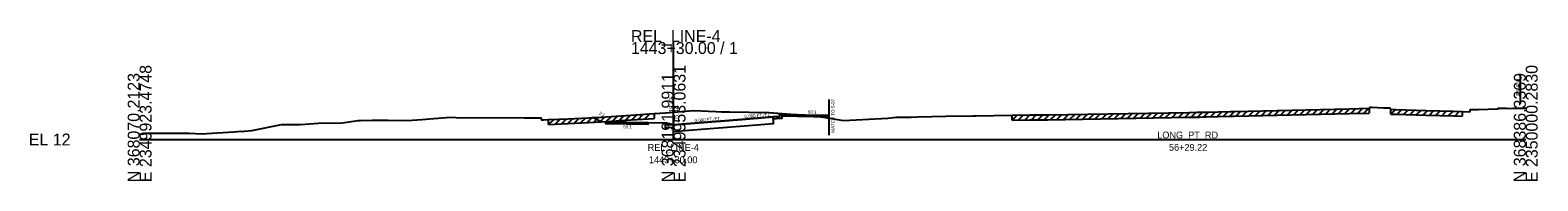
# Model space of a CAD drawing. Extents: x -26 to 2350146, y -10 to 368200.
# Drawn here: x 1974.3 to 2328.2, y 3490.3 to 3525.7 of the extents above; entities that cross this region are included whole.
import ezdxf

# ---------------------------------------------------------------- set-up
doc = ezdxf.new("R2010")
doc.units = 0
for name, color, linetype in [('RD_GPK_XS_Cell', 7, 'Continuous'), ('RD_XS_Base', 7, 'Continuous'), ('RD_XS_CurbBase', 7, 'Continuous'), ('RD_XS_CurbFront', 7, 'Continuous'), ('RD_XS_CurbTop', 7, 'Continuous'), ('RD_XS_EarthShd', 7, 'Continuous'), ('RD_XS_EwShp', 7, 'Continuous'), ('RD_XS_ExGround', 7, 'Continuous'), ('RD_XS_ExPaveRet', 7, 'Continuous'), ('RD_XS_ExRW', 7, 'Continuous'), ('RD_XS_Pave', 7, 'Continuous'), ('RD_XS_PaveShd', 7, 'Continuous'), ('RD_XS_SW', 7, 'Continuous'), ('RD_XS_SWbase', 7, 'Continuous'), ('RD_XS_TieSlope', 7, 'Continuous'), ('RD_XS_TX_Elev_EX', 7, 'Continuous'), ('RD_XS_TX_Elev_PR', 7, 'Continuous'), ('RD_XS_TX_MatchLine', 7, 'Continuous'), ('RD_XS_TX_Slope', 7, 'Continuous'), ('RD_XS_TX_Station', 7, 'Continuous'), ('RD_XS_TX_TOC', 7, 'Continuous')]:
    doc.layers.add(name, color=color, linetype=linetype)

msp = doc.modelspace()

# ---------------------------------------------------------------- linework, layer by layer
at = {"layer": 'RD_GPK_XS_Cell'}
for p, q in [((2125.32, 3500), (2125.32, 3522.86)), ((2000, 3500), (2125.32, 3500)), ((2125.32, 3500), (2325.32, 3500))]:
    msp.add_line(p, q, dxfattribs=at)
at = {"layer": 'RD_XS_Base'}
for p, q in [((2144.86, 3503.36), (2128.86, 3502.08)), ((2148.73, 3503.67), (2144.86, 3503.36)), ((2148.73, 3505.31), (2148.73, 3503.67)), ((2125.32, 3501.8), (2125.32, 3502.92)), ((2128.86, 3502.08), (2125.32, 3501.8))]:
    msp.add_line(p, q, dxfattribs=at)
at = {"layer": 'RD_XS_CurbBase'}
for p, q in [((2123.32, 3503.83), (2123.32, 3502.83)), ((2150.22, 3504.9), (2148.73, 3504.79)), ((2150.72, 3504.9), (2150.22, 3504.9)), ((2150.72, 3505.9), (2150.72, 3504.9)), ((2123.32, 3502.83), (2123.82, 3502.83)), ((2123.82, 3502.83), (2125.32, 3502.92))]:
    msp.add_line(p, q, dxfattribs=at)
at = {"layer": 'RD_XS_CurbFront'}
for p, q in [((2125.32, 3502.92), (2125.32, 3503.42)), ((2148.73, 3504.79), (2148.73, 3505.29))]:
    msp.add_line(p, q, dxfattribs=at)
at = {"layer": 'RD_XS_CurbTop'}
for p, q in [((2123.82, 3503.83), (2123.32, 3503.83)), ((2123.9, 3503.33), (2123.82, 3503.83)), ((2125.32, 3503.42), (2123.9, 3503.33)), ((2125.32, 3503.44), (2125.32, 3503.42)), ((2148.73, 3505.29), (2150.14, 3505.4)), ((2148.73, 3505.31), (2148.73, 3505.29)), ((2150.14, 3505.4), (2150.22, 3505.9)), ((2150.22, 3505.9), (2150.72, 3505.9))]:
    msp.add_line(p, q, dxfattribs=at)
at = {"layer": 'RD_XS_EarthShd'}
for p, q in [((2109.32, 3504.11), (2108.32, 3504.13)), ((2123.32, 3503.83), (2119.32, 3503.91))]:
    msp.add_line(p, q, dxfattribs=at)
at = {"layer": 'RD_XS_EwShp'}
for points in [[(2123.42, 3506.27), (2125.32, 3506.42), (2130.02, 3506.78), (2135.34, 3506.55), (2136.59, 3506.5), (2138.46, 3506.5), (2147.67, 3506.36), (2154.34, 3505.83), (2150.72, 3505.9), (2150.22, 3505.9), (2150.14, 3505.4), (2148.73, 3505.31), (2141.32, 3504.72), (2125.32, 3503.42), (2123.9, 3503.33), (2123.82, 3503.83), (2123.32, 3503.83), (2119.32, 3503.91), (2109.32, 3504.11), (2108.32, 3504.13), (2106.27, 3505.16), (2108.36, 3505.27), (2115.36, 3505.72), (2120.75, 3506.07)], [(2109.32, 3504.11), (2109.32, 3503.78), (2119.32, 3503.58), (2119.32, 3503.91)], [(2125.32, 3503.42), (2123.9, 3503.33), (2123.82, 3503.83), (2123.32, 3503.83), (2123.32, 3502.83), (2123.82, 3502.83), (2125.32, 3502.92)], [(2125.32, 3501.8), (2125.32, 3502.92), (2125.32, 3503.42), (2141.32, 3504.72), (2148.73, 3505.31), (2148.73, 3504.79), (2148.73, 3503.67), (2144.86, 3503.36), (2128.86, 3502.08)], [(2150.72, 3505.57), (2150.72, 3504.9), (2150.22, 3504.9), (2148.73, 3504.79), (2148.73, 3505.31), (2150.14, 3505.4), (2150.22, 3505.9), (2150.72, 3505.9)], [(2154.34, 3505.83), (2158.06, 3505.53), (2159.07, 3505.4), (2150.72, 3505.57), (2150.72, 3505.9)], [(2159.07, 3505.4), (2159.8, 3505.31), (2160.52, 3505.26), (2161.84, 3505.03), (2161.84, 3505.35)]]:
    msp.add_lwpolyline(points, close=True, dxfattribs=at)
at = {"layer": 'RD_XS_ExGround'}
msp.add_lwpolyline([(2000, 3501.25), (2000.38, 3501.29), (2001.98, 3501.46), (2002.55, 3501.5), (2004.55, 3501.5), (2010.26, 3501.49), (2010.63, 3501.5), (2011.6, 3501.46), (2014.52, 3501.35), (2022.11, 3501.77), (2023.81, 3501.96), (2024.19, 3501.92), (2024.58, 3501.96), (2026.37, 3502.15), (2033.32, 3503.5), (2037.76, 3503.49), (2041.95, 3503.83), (2047.54, 3503.9), (2051.32, 3504.5), (2051.81, 3504.5), (2054.55, 3504.51), (2056.8, 3504.51), (2058.36, 3504.51), (2062.81, 3504.5), (2066.25, 3504.69), (2072.91, 3505.28), (2075.62, 3505.11), (2082.34, 3505.17), (2090.29, 3505.08), (2093.59, 3505.1), (2094.15, 3505.09), (2094.32, 3504.59), (2094.9, 3504.62), (2095.99, 3504.66), (2100.61, 3504.88), (2105.35, 3505.11), (2108.36, 3505.27), (2115.36, 3505.72), (2120.75, 3506.07), (2123.42, 3506.27), (2125.32, 3506.42), (2130.02, 3506.78), (2135.34, 3506.55), (2136.59, 3506.5), (2138.46, 3506.5), (2147.67, 3506.36), (2158.06, 3505.53), (2159.8, 3505.31), (2160.52, 3505.26), (2165.16, 3504.44), (2175.59, 3505.02), (2177.67, 3505.28), (2179.39, 3505.27), (2181.05, 3505.28), (2182.62, 3505.3), (2189.24, 3505.5), (2195.52, 3505.52), (2196.26, 3505.53), (2204.8, 3505.7), (2208.92, 3505.79), (2213.11, 3505.79), (2246.21, 3506.36), (2248.09, 3506.4), (2248.78, 3506.41), (2250.35, 3506.45), (2255.98, 3506.58), (2256.88, 3506.6), (2283.86, 3507.21), (2288.59, 3507.32), (2288.78, 3507.62), (2289.2, 3507.62), (2291.95, 3507.47), (2293.02, 3507.42), (2293.44, 3507.42), (2293.64, 3507.12), (2294.83, 3507.08), (2301.92, 3506.82), (2308.39, 3506.67), (2310.37, 3506.6), (2312.16, 3506.52), (2312.35, 3507.02), (2312.94, 3507.02), (2314.12, 3507.04), (2318.82, 3507.2), (2318.82, 3507.35), (2320.84, 3507.37), (2321.14, 3507.31), (2322.36, 3507.35), (2325.32, 3507.38)], dxfattribs=at)
at = {"layer": 'RD_XS_ExPaveRet'}
for p, q in [((2260.3, 3505.54), (2261.47, 3506.71)), ((2261.8, 3505.57), (2262.97, 3506.74)), ((2263.3, 3505.6), (2264.47, 3506.77)), ((2264.8, 3505.64), (2265.97, 3506.81)), ((2266.3, 3505.67), (2267.47, 3506.84)), ((2267.8, 3505.71), (2268.97, 3506.88)), ((2269.3, 3505.74), (2270.47, 3506.91)), ((2270.8, 3505.77), (2271.97, 3506.94)), ((2272.3, 3505.81), (2273.47, 3506.98)), ((2273.8, 3505.84), (2274.97, 3507.01)), ((2275.3, 3505.88), (2276.47, 3507.05)), ((2276.8, 3505.91), (2277.97, 3507.08)), ((2278.3, 3505.94), (2279.47, 3507.11)), ((2279.8, 3505.98), (2280.97, 3507.15)), ((2281.3, 3506.01), (2282.47, 3507.18)), ((2282.8, 3506.05), (2283.97, 3507.22)), ((2284.3, 3506.08), (2285.47, 3507.25)), ((2285.8, 3506.11), (2286.97, 3507.28)), ((2287.3, 3506.15), (2288.47, 3507.32)), ((2288.59, 3507.32), (2288.59, 3506.17)), ((2293.64, 3505.97), (2293.64, 3507.12)), ((2293.64, 3505.97), (2294.74, 3507.08)), ((2295.14, 3505.92), (2296.24, 3507.03)), ((2296.64, 3505.87), (2297.74, 3506.97)), ((2298.14, 3505.81), (2299.24, 3506.92)), ((2299.64, 3505.76), (2300.74, 3506.86)), ((2301.14, 3505.71), (2302.24, 3506.81)), ((2302.64, 3505.66), (2303.75, 3506.78)), ((2304.14, 3505.62), (2305.25, 3506.74)), ((2305.64, 3505.59), (2306.75, 3506.71)), ((2095.99, 3503.52), (2097.19, 3504.72)), ((2095.99, 3503.52), (2095.99, 3504.66)), ((2095.99, 3503.52), (2100.61, 3503.74)), ((2097.49, 3503.59), (2098.69, 3504.79)), ((2098.99, 3503.66), (2100.19, 3504.86)), ((2100.49, 3503.73), (2101.69, 3504.93)), ((2100.61, 3503.74), (2105.35, 3503.97)), ((2101.99, 3503.8), (2103.19, 3505)), ((2103.49, 3503.88), (2104.69, 3505.08)), ((2104.99, 3503.95), (2106.2, 3505.15)), ((2105.35, 3503.97), (2108.36, 3504.13)), ((2106.49, 3504.03), (2107.7, 3505.24)), ((2107.99, 3504.11), (2109.21, 3505.33)), ((2108.36, 3504.13), (2115.36, 3504.58)), ((2109.49, 3504.2), (2110.71, 3505.42)), ((2110.99, 3504.3), (2112.21, 3505.52)), ((2112.49, 3504.4), (2113.71, 3505.62)), ((2113.99, 3504.49), (2115.21, 3505.72)), ((2115.36, 3504.58), (2120.75, 3504.93)), ((2115.49, 3504.59), (2116.71, 3505.81)), ((2116.99, 3504.69), (2118.21, 3505.91)), ((2118.49, 3504.78), (2119.71, 3506)), ((2120.75, 3506.07), (2120.75, 3504.93)), ((2204.8, 3504.56), (2205.97, 3505.72)), ((2204.8, 3504.56), (2204.8, 3505.7)), ((2204.8, 3504.56), (2208.92, 3504.64)), ((2206.3, 3504.59), (2207.47, 3505.76)), ((2207.8, 3504.62), (2208.97, 3505.79)), ((2208.92, 3504.64), (2213.11, 3504.65)), ((2209.3, 3504.64), (2210.45, 3505.79)), ((2210.8, 3504.65), (2211.95, 3505.79)), ((2212.3, 3504.65), (2213.45, 3505.8)), ((2213.11, 3504.65), (2246.21, 3505.22)), ((2213.8, 3504.66), (2214.97, 3505.83)), ((2215.3, 3504.69), (2216.47, 3505.85)), ((2216.8, 3504.72), (2217.97, 3505.88)), ((2218.3, 3504.74), (2219.47, 3505.9)), ((2219.8, 3504.77), (2220.97, 3505.93)), ((2221.3, 3504.79), (2222.47, 3505.96)), ((2222.8, 3504.82), (2223.97, 3505.98)), ((2224.3, 3504.84), (2225.47, 3506.01)), ((2225.8, 3504.87), (2226.97, 3506.03)), ((2227.3, 3504.9), (2228.47, 3506.06)), ((2228.8, 3504.92), (2229.97, 3506.08)), ((2230.3, 3504.95), (2231.47, 3506.11)), ((2231.8, 3504.97), (2232.97, 3506.14)), ((2233.3, 3505), (2234.47, 3506.16)), ((2234.8, 3505.02), (2235.97, 3506.19)), ((2236.3, 3505.05), (2237.47, 3506.21)), ((2237.8, 3505.08), (2238.97, 3506.24)), ((2239.3, 3505.1), (2240.47, 3506.26)), ((2240.8, 3505.13), (2241.97, 3506.29)), ((2242.3, 3505.15), (2243.47, 3506.32)), ((2243.8, 3505.18), (2244.97, 3506.34)), ((2245.3, 3505.2), (2246.47, 3506.37)), ((2246.21, 3505.22), (2248.09, 3505.26)), ((2246.8, 3505.23), (2247.97, 3506.4)), ((2248.09, 3505.26), (2248.78, 3505.27)), ((2248.3, 3505.26), (2249.47, 3506.43)), ((2248.78, 3505.27), (2250.35, 3505.31)), ((2249.8, 3505.29), (2250.97, 3506.46)), ((2250.35, 3505.31), (2255.98, 3505.44)), ((2251.3, 3505.33), (2252.47, 3506.5)), ((2252.8, 3505.36), (2253.97, 3506.53)), ((2254.3, 3505.4), (2255.47, 3506.57)), ((2255.8, 3505.43), (2256.97, 3506.6)), ((2255.98, 3505.44), (2256.88, 3505.46)), ((2256.88, 3505.46), (2283.86, 3506.07)), ((2257.3, 3505.47), (2258.47, 3506.64)), ((2258.8, 3505.5), (2259.97, 3506.67)), ((2283.86, 3506.07), (2288.59, 3506.17)), ((2293.64, 3505.97), (2294.83, 3505.93)), ((2294.83, 3505.93), (2301.92, 3505.68)), ((2301.92, 3505.68), (2308.39, 3505.52)), ((2307.14, 3505.55), (2308.25, 3506.67)), ((2308.39, 3505.52), (2310.37, 3505.46)), ((2308.64, 3505.51), (2309.74, 3506.62)), ((2310.37, 3506.6), (2310.37, 3505.46))]:
    msp.add_line(p, q, dxfattribs=at)
at = {"layer": 'RD_XS_ExRW'}
msp.add_line((2324.08, 3508.37), (2324.08, 3515.37), dxfattribs=at)
at = {"layer": 'RD_XS_Pave'}
for p, q in [((2161.84, 3501.02), (2161.84, 3509.37)), ((2125.32, 3503.44), (2141.32, 3504.72))]:
    msp.add_line(p, q, dxfattribs=at)
at = {"layer": 'RD_XS_PaveShd'}
msp.add_line((2148.73, 3505.31), (2141.32, 3504.72), dxfattribs=at)
at = {"layer": 'RD_XS_SW'}
for p, q in [((2119.32, 3503.91), (2109.32, 3504.11)), ((2150.72, 3505.9), (2161.84, 3505.68))]:
    msp.add_line(p, q, dxfattribs=at)
at = {"layer": 'RD_XS_SWbase'}
for p, q in [((2109.32, 3504.11), (2109.32, 3503.78)), ((2109.32, 3503.78), (2119.32, 3503.58)), ((2119.32, 3503.58), (2119.32, 3503.91)), ((2150.72, 3505.57), (2161.84, 3505.35))]:
    msp.add_line(p, q, dxfattribs=at)
at = {"layer": 'RD_XS_TieSlope'}
msp.add_line((2108.32, 3504.13), (2106.27, 3505.16), dxfattribs=at)

# ---------------------------------------------------------------- texts
at = {"layer": 'RD_GPK_XS_Cell'}
for s, p in [('REL_LINE-4', (2115.32, 3522.86)), ('1443+30.00 / 1', (2115.32, 3520.06)), ('EL 12', (1974, 3498.6))]:
    msp.add_text(s, height=2.8, dxfattribs=at).set_placement(p)
for s, p in [('E 2349923.4748', (2002.8, 3490)), ('E 2350000.2830', (2328.12, 3490)), ('N 368070.2123', (2000, 3490)), ('N 368191.9911', (2125.32, 3490)), ('E 2349953.0631', (2128.12, 3490)), ('N 368386.3369', (2325.32, 3490))]:
    msp.add_text(s, height=2.8, rotation=90, dxfattribs=at).set_placement(p)
at = {"layer": 'RD_XS_ExRW'}
msp.add_text('EX. R/W ', height=0.75, rotation=90, dxfattribs=at).set_placement((2323.78, 3510.32))
at = {"layer": 'RD_XS_TX_Elev_EX'}
msp.add_text('18.42', height=1, rotation=90, dxfattribs=at).set_placement((2125.26, 3506.42))
at = {"layer": 'RD_XS_TX_Elev_PR'}
msp.add_text(' 15.44', height=1.2, rotation=90, dxfattribs=at).set_placement((2126.52, 3503.44))
at = {"layer": 'RD_XS_TX_MatchLine'}
msp.add_text('MATCH TO S-97', height=0.75, rotation=90, dxfattribs=at).set_placement((2163.1, 3501.63))
at = {"layer": 'RD_XS_TX_Slope'}
for s, rotation, p in [('50:1', 358.8542, (2156.84, 3506.11)), ('2:1', 333.4349, (2107.72, 3505.93)), ('50:1', 358.8542, (2113.49, 3502.64)), ('0.080 FT./FT.', 4.5739, (2130.28, 3504.08)), ('0.080 FT./FT.', 4.5739, (2141.99, 3505.02))]:
    msp.add_text(s, height=0.75, rotation=rotation, dxfattribs=at).set_placement(p)
at = {"layer": 'RD_XS_TX_Station'}
for s, p in [('LONG_PT_RD', (2238.84, 3500.26)), ('REL_LINE-4', (2119.25, 3497.34)), ('56+29.22', (2241.59, 3497.36)), ('1443+30.00', (2119.55, 3494.44))]:
    msp.add_text(s, height=1.6, dxfattribs=at).set_placement(p)
at = {"layer": 'RD_XS_TX_TOC'}
for p in [(2123.87, 3503.78), (2149.96, 3505.66)]:
    msp.add_text('TOCLT', height=0.05, dxfattribs=at).set_placement(p)

doc.saveas('drawing.dxf')
